(* Logix 5000 project; controller Example_PLC vendor 1 type 14 code 77 rev 19.11; software revision 19.01; part 5 of 6 *)
(* tags used below, declared in another part *)
   DISABLE : BOOL;
   ENABLE : BOOL;
   from : BOOL;
   Position : DINT;
   shutdown : BOOL;

ADD_ON_INSTRUCTION AKD_Set_Units   (* revision 2.2, ExecutePrescan, ExecuteEnableInFalse *)
// Set Drive Units for Motion Commands
// Revision note:
// Clean up instruction, especially for error recovery.
VAR_IN_OUT
   Axis : AKD_Axis; {required}
END_VAR
VAR_INPUT
   Units : SINT; {required}   // Drive Units (0=Counts 16 bit)
END_VAR
VAR_OUTPUT
   DN : BOOL; {access Read Only, visible}   // Command Successfully Initiated
   ER : BOOL; {access Read Only, visible}   // Error
END_VAR
VAR
   Set_POSUNIT : AKD_Set_Attribute := (Attribute_Number := 4);
   Set_PROFUNIT : AKD_Set_Attribute := (Attribute_Number := 5);
   Step : SINT;   // Sequence Step Number
   OS_Start_Sequence : BOOL;
   Profile_Ratio : DINT;   // The number of actual feedback counts per second or second2 equal to one velocity or acceleration unit
   Position_Ratio : DINT;   // The number of actual position feedback counts equal to one position unit
   Invalid_Input : BOOL;   // Invalid Units Input
END_VAR

ROUTINE EnableInFalse   (* ladder *)
// EnableIn_False
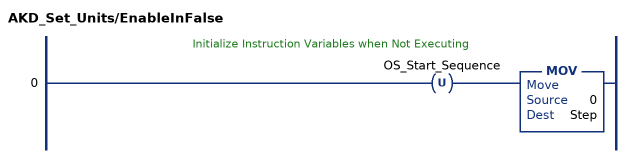
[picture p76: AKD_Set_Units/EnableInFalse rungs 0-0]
   // Initialize Instruction Variables when Not Executing
   0: OTU(OS_Start_Sequence)MOV(0,Step);
END_ROUTINE

ROUTINE Logic   (* ladder *)
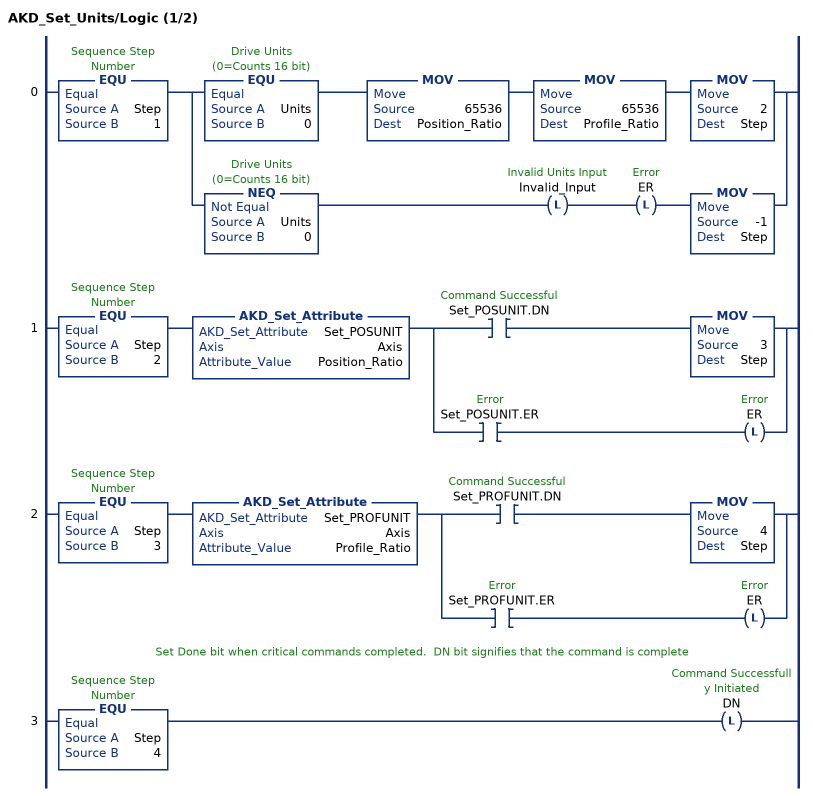
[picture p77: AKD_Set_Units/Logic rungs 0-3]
   0: EQU(Step,1)[EQU(Units,0) MOV(65536,Position_Ratio) MOV(65536,Profile_Ratio) MOV(2,Step) ,NEQ(Units,0) OTL(Invalid_Input) OTL(ER) MOV(-1,Step) ];
   1: EQU(Step,2)AKD_Set_Attribute(Set_POSUNIT,Axis,Position_Ratio)[XIC(Set_POSUNIT.DN) MOV(3,Step) ,XIC(Set_POSUNIT.ER) OTL(ER) ];
   2: EQU(Step,3)AKD_Set_Attribute(Set_PROFUNIT,Axis,Profile_Ratio)[XIC(Set_PROFUNIT.DN) MOV(4,Step) ,XIC(Set_PROFUNIT.ER) OTL(ER) ];
   // Set Done bit when critical commands completed.  DN bit signifies that the command is complete
   3: EQU(Step,4)OTL(DN);
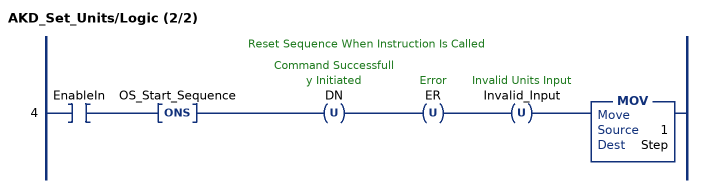
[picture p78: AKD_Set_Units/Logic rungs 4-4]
   // Reset Sequence When Instruction Is Called
   4: XIC(EnableIn)ONS(OS_Start_Sequence)OTU(DN)OTU(ER)OTU(Invalid_Input)MOV(1,Step);
END_ROUTINE

ROUTINE Prescan   (* ladder *)
// Prescan
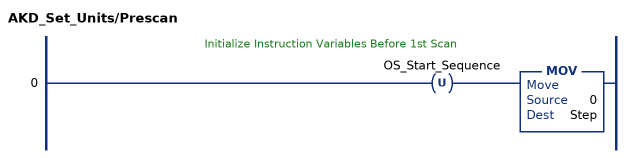
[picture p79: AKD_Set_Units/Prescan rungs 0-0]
   // Initialize Instruction Variables Before 1st Scan
   0: OTU(OS_Start_Sequence)MOV(0,Step);
END_ROUTINE
END_ADD_ON_INSTRUCTION

ADD_ON_INSTRUCTION AKD_Set_Velocity   (* revision 2.1, ExecutePrescan, ExecuteEnableInFalse *)
// Set Drive Velocity
// Revision note:
// Don't error if Command_Timeout preset is 0
VAR_OUTPUT
   DN : BOOL; {access Read Only, visible}   // Command Successful
   ER : BOOL; {access Read Only, visible}   // Error
END_VAR
VAR_IN_OUT
   Axis : AKD_Axis; {required}
END_VAR
VAR_INPUT
   Velocity : DINT; {required}   // Velocity
END_VAR
VAR
   Response_Bytes : SINT[8];
   OS_LoadStart : BOOL;
   Velocity_Internal : DINT;   // Scaled Velocity Value for Drive
   Command_Timeout : TIMER := (PRE := 100);   // Timeout Timer
   Command_Message_Type : SINT;   // Command Message Type
   Command_Axis_Number : SINT;   // Command Axis Number
   Response_Message_Type : SINT;   // Response Message Type
   Response_Axis_Number : SINT;   // Response Axis Number
   Command_Bytes : SINT[8];
   Step : SINT;
END_VAR

ROUTINE EnableInFalse   (* ladder *)
// EnableIn_False
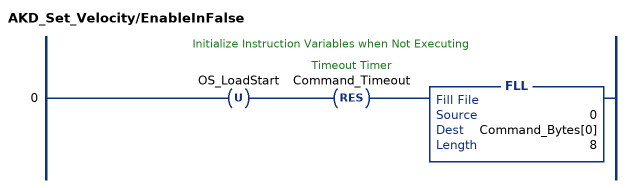
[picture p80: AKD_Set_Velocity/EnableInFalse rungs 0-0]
   // Initialize Instruction Variables when Not Executing
   0: OTU(OS_LoadStart)RES(Command_Timeout)FLL(0,Command_Bytes[0],8);
END_ROUTINE

ROUTINE Logic   (* ladder *)
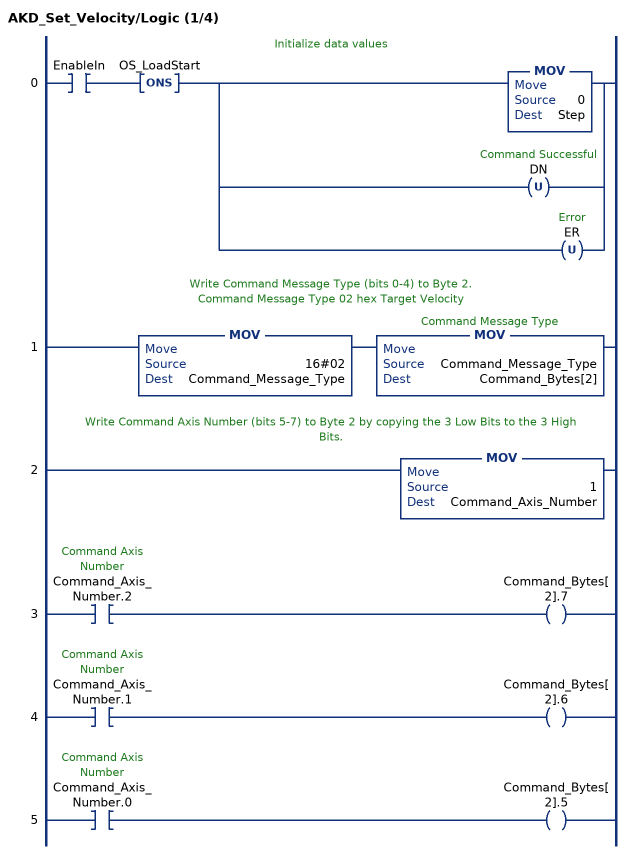
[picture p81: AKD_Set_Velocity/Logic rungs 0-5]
   // Initialize data values
   0: XIC(EnableIn)ONS(OS_LoadStart)[MOV(0,Step) ,OTU(DN) ,OTU(ER) ];
   // Write Command Message Type (bits 0-4) to Byte 2.
   // Command Message Type 02 hex Target Velocity
   1: MOV(16#02,Command_Message_Type)MOV(Command_Message_Type,Command_Bytes[2]);
   // Write Command Axis Number (bits 5-7) to Byte 2 by copying the 3 Low Bits to the 3 High Bits.
   2: MOV(1,Command_Axis_Number);
   3: XIC(Command_Axis_Number.2)OTE(Command_Bytes[2].7);
   4: XIC(Command_Axis_Number.1)OTE(Command_Bytes[2].6);
   5: XIC(Command_Axis_Number.0)OTE(Command_Bytes[2].5);
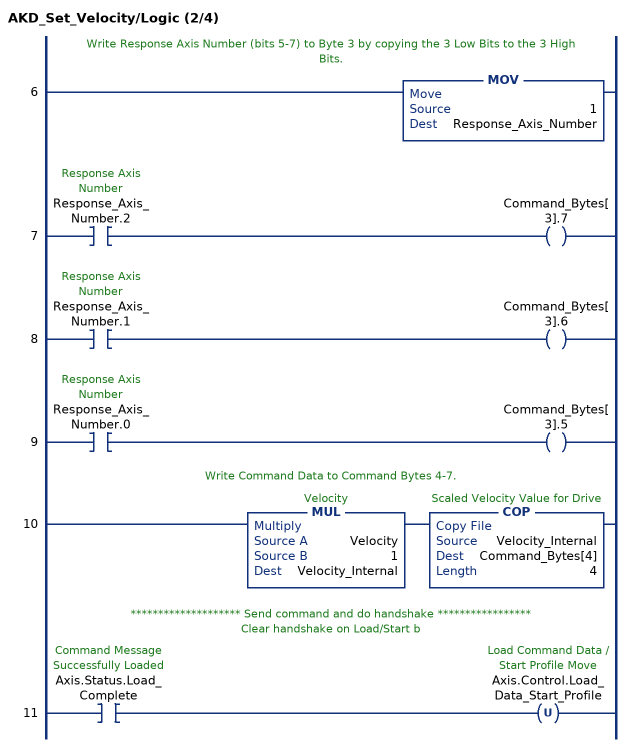
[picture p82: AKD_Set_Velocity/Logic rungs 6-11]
   // Write Response Axis Number (bits 5-7) to Byte 3 by copying the 3 Low Bits to the 3 High Bits.
   6: MOV(1,Response_Axis_Number);
   7: XIC(Response_Axis_Number.2)OTE(Command_Bytes[3].7);
   8: XIC(Response_Axis_Number.1)OTE(Command_Bytes[3].6);
   9: XIC(Response_Axis_Number.0)OTE(Command_Bytes[3].5);
   // Write Command Data to Command Bytes 4-7.
   10: MUL(Velocity,1,Velocity_Internal)COP(Velocity_Internal,Command_Bytes[4],4);
   // ******************** Send command and do handshake *****************
   // Clear handshake on Load/Start b
   11: XIC(Axis.Status.Load_Complete)OTU(Axis.Control.Load_Data_Start_Profile);
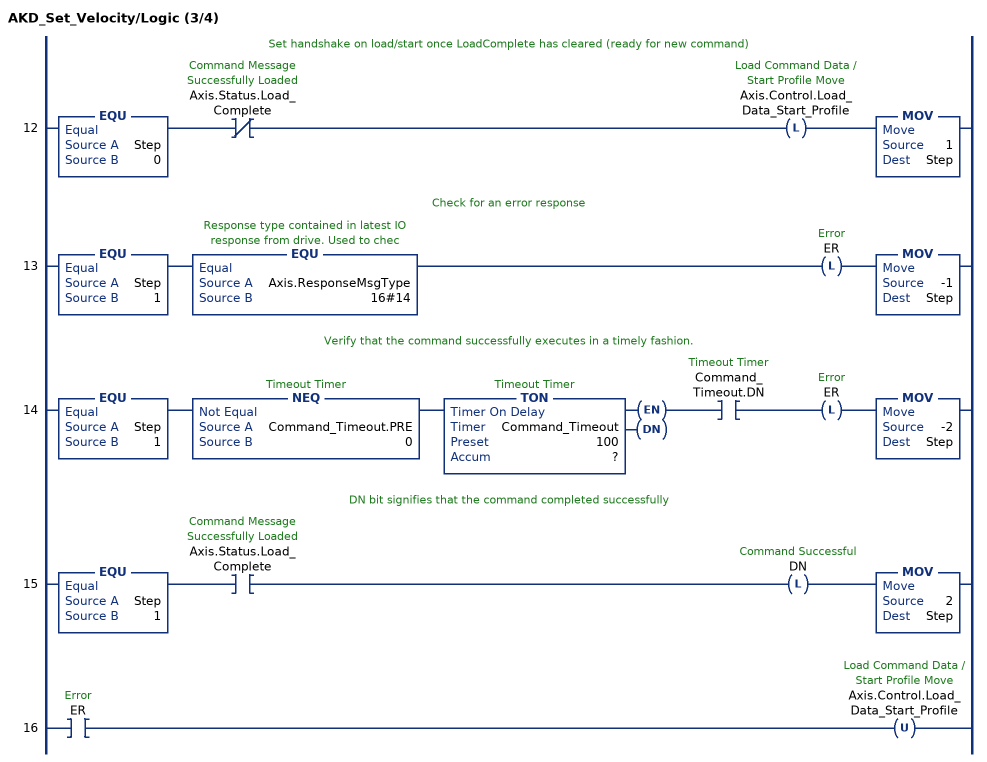
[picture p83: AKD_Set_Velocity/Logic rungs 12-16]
   // Set handshake on load/start once LoadComplete has cleared (ready for new command)
   12: EQU(Step,0)XIO(Axis.Status.Load_Complete)OTL(Axis.Control.Load_Data_Start_Profile)MOV(1,Step);
   // Check for an error response
   13: EQU(Step,1)EQU(Axis.ResponseMsgType,16#14)OTL(ER)MOV(-1,Step);
   // Verify that the command successfully executes in a timely fashion.
   14: EQU(Step,1)NEQ(Command_Timeout.PRE,0)TON(Command_Timeout,?,?)XIC(Command_Timeout.DN)OTL(ER)MOV(-2,Step);
   // DN bit signifies that the command completed successfully
   15: EQU(Step,1)XIC(Axis.Status.Load_Complete)OTL(DN)MOV(2,Step);
   16: XIC(ER)OTU(Axis.Control.Load_Data_Start_Profile);
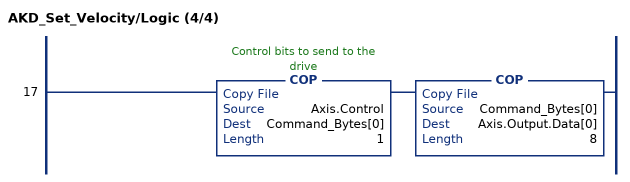
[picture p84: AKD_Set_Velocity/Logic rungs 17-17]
   17: COP(Axis.Control,Command_Bytes[0],1)COP(Command_Bytes[0],Axis.Output.Data[0],8);
END_ROUTINE

ROUTINE Prescan   (* ladder *)
// Prescan
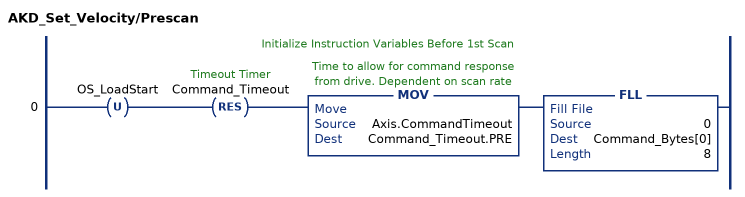
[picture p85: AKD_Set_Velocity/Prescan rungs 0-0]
   // Initialize Instruction Variables Before 1st Scan
   0: OTU(OS_LoadStart)RES(Command_Timeout)MOV(Axis.CommandTimeout,Command_Timeout.PRE)FLL(0,Command_Bytes[0],8);
END_ROUTINE
END_ADD_ON_INSTRUCTION

ADD_ON_INSTRUCTION AKD_Shutdown   (* revision 4.0, ExecutePrescan, ExecuteEnableInFalse *)
// Motion Hard Stop
// Revision note:
// There was a race with the Axis.Control.Hardstop bit.  I removed it from EnableInFalse and did the reset in the logic
VAR_OUTPUT
   DN : BOOL; {access Read Only, visible}   // Command Successful
   ER : BOOL; {access Read Only, visible}   // Error
END_VAR
VAR_IN_OUT
   Axis : AKD_Axis; {required}
END_VAR
VAR
   Command_Timeout : TIMER := (PRE := 2000);   // Timeout Timer
   Step : DINT; {access None}
END_VAR

ROUTINE EnableInFalse   (* ladder *)
// Enable In False
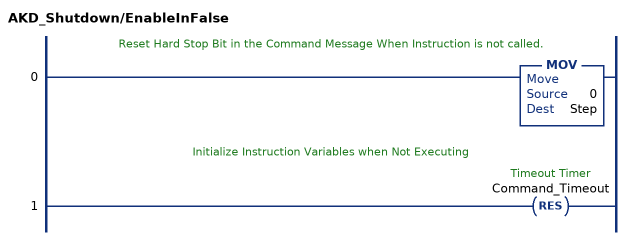
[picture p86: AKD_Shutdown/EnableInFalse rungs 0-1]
   // Reset Hard Stop Bit in the Command Message When Instruction is not called.
   0: MOV(0,Step);
   // Initialize Instruction Variables when Not Executing
   1: RES(Command_Timeout);
END_ROUTINE

ROUTINE Logic   (* ladder *)
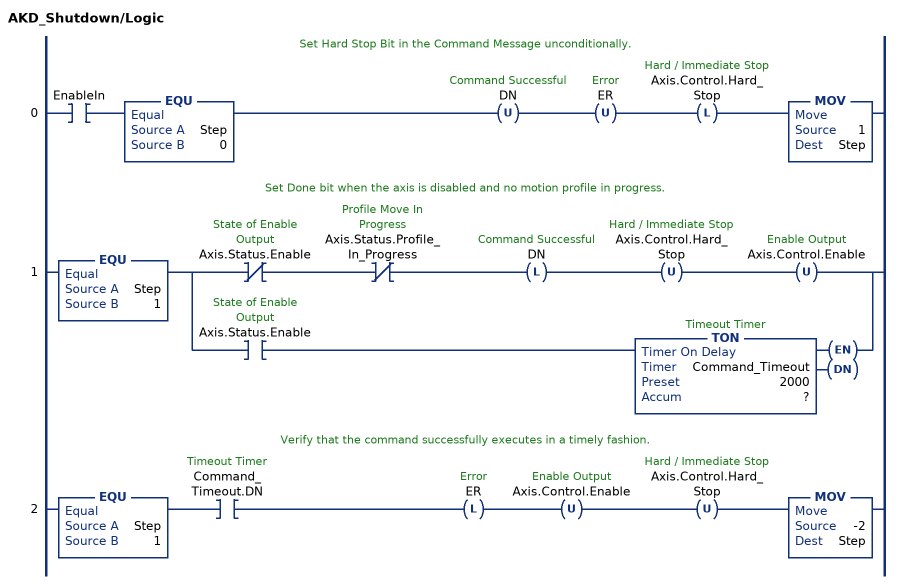
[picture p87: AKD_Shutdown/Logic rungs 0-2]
   // Set Hard Stop Bit in the Command Message unconditionally.
   0: XIC(EnableIn)EQU(Step,0)OTU(DN)OTU(ER)OTL(Axis.Control.Hard_Stop)MOV(1,Step);
   // Set Done bit when the axis is disabled and no motion profile in progress.
   1: EQU(Step,1)[XIO(Axis.Status.Enable) XIO(Axis.Status.Profile_In_Progress) OTL(DN) OTU(Axis.Control.Hard_Stop) OTU(Axis.Control.Enable) ,XIC(Axis.Status.Enable) TON(Command_Timeout,?,?) ];
   // Verify that the command successfully executes in a timely fashion.
   2: EQU(Step,1)XIC(Command_Timeout.DN)OTL(ER)OTU(Axis.Control.Enable)OTU(Axis.Control.Hard_Stop)MOV(-2,Step);
END_ROUTINE

ROUTINE Prescan   (* ladder *)
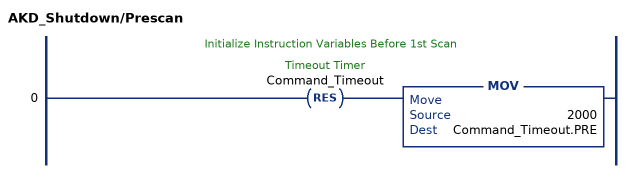
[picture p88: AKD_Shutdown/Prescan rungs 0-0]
   // Initialize Instruction Variables Before 1st Scan
   0: RES(Command_Timeout)MOV(2000,Command_Timeout.PRE);
END_ROUTINE
END_ADD_ON_INSTRUCTION

ADD_ON_INSTRUCTION AKD_Shutdown_Reset   (* revision 2.1, ExecutePrescan, ExecuteEnableInFalse *)
// Reset Drive after a Shutdown Command
// Revision note:
// Set disable timeout to 100ms
VAR_OUTPUT
   DN : BOOL; {access Read Only, visible}   // Command Successful
   ER : BOOL; {access Read Only, visible}   // Error
END_VAR
VAR_IN_OUT
   Axis : AKD_Axis; {required}
END_VAR
VAR
   Fault_Reset : AKD_Fault_Reset;
   Set_Disable : AKD_Disable;
   Step : SINT;   // Sequence Step Number
   OS_Start_Sequence : BOOL;
   Command_Timeout : TIMER := (PRE := 10000);
   Disable_Timer : TIMER := (PRE := 100);
END_VAR

ROUTINE EnableInFalse   (* ladder *)
// EnableIn_False
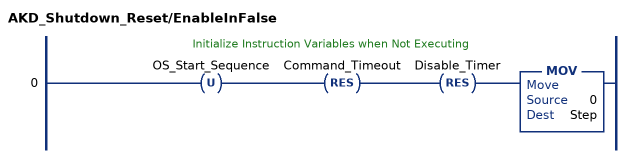
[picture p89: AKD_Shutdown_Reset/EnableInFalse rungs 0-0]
   // Initialize Instruction Variables when Not Executing
   0: OTU(OS_Start_Sequence)RES(Command_Timeout)RES(Disable_Timer)MOV(0,Step);
END_ROUTINE

ROUTINE Logic   (* ladder *)
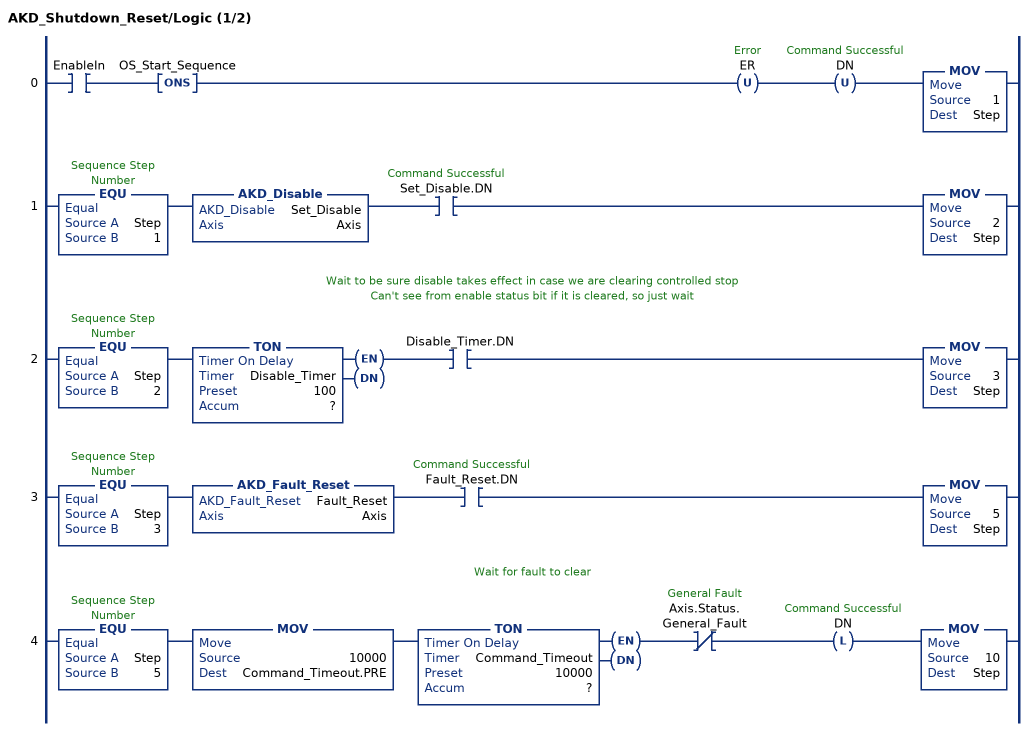
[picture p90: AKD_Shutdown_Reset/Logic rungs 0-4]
   0: XIC(EnableIn)ONS(OS_Start_Sequence)OTU(ER)OTU(DN)MOV(1,Step);
   1: EQU(Step,1)AKD_Disable(Set_Disable,Axis)XIC(Set_Disable.DN)MOV(2,Step);
   // Wait to be sure disable takes effect in case we are clearing controlled stop
   // Can't see from enable status bit if it is cleared, so just wait
   2: EQU(Step,2)TON(Disable_Timer,?,?)XIC(Disable_Timer.DN)MOV(3,Step);
   3: EQU(Step,3)AKD_Fault_Reset(Fault_Reset,Axis)XIC(Fault_Reset.DN)MOV(5,Step);
   // Wait for fault to clear
   4: EQU(Step,5)MOV(10000,Command_Timeout.PRE)TON(Command_Timeout,?,?)XIO(Axis.Status.General_Fault)OTL(DN)MOV(10,Step);
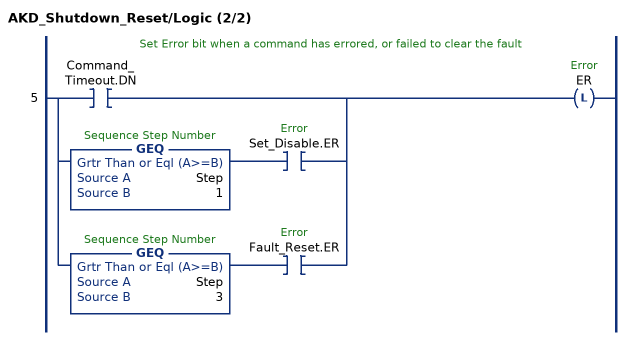
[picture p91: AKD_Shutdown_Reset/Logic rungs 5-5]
   // Set Error bit when a command has errored, or failed to clear the fault
   5: [XIC(Command_Timeout.DN) ,GEQ(Step,1) XIC(Set_Disable.ER) ,GEQ(Step,3) XIC(Fault_Reset.ER) ]OTL(ER);
END_ROUTINE

ROUTINE Prescan   (* ladder *)
// Prescan
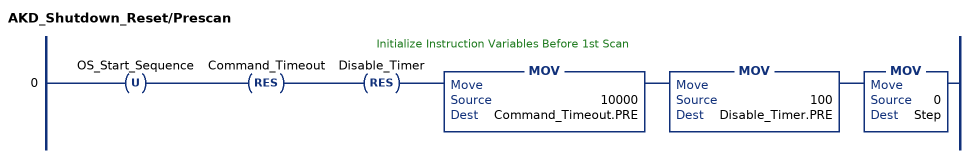
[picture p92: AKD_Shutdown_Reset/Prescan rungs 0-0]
   // Initialize Instruction Variables Before 1st Scan
   0: OTU(OS_Start_Sequence)RES(Command_Timeout)RES(Disable_Timer)MOV(10000,Command_Timeout.PRE)MOV(100,Disable_Timer.PRE)MOV(0,Step);
END_ROUTINE
END_ADD_ON_INSTRUCTION

ADD_ON_INSTRUCTION AKD_Stop_Smooth   (* revision 4.0, ExecutePrescan, ExecuteEnableInFalse *)
// Motion Smooth Stop
// Revision note:
// There was a race with the control word smooth stop bit.  I removed the logic in "EnableInFalse" and did the reset as part of the normal logic.
VAR_OUTPUT
   DN : BOOL; {access Read Only, visible}   // Command Successful
   ER : BOOL; {access Read Only, visible}   // Error
END_VAR
VAR_IN_OUT
   Axis : AKD_Axis; {required}
END_VAR
VAR_OUTPUT
   IP : BOOL; {access Read Only, visible}   // In Progress
END_VAR
VAR
   One_SHT : BOOL; {access None}
   Step : DINT; {access None}
END_VAR

ROUTINE EnableInFalse   (* ladder *)
// Enable In False
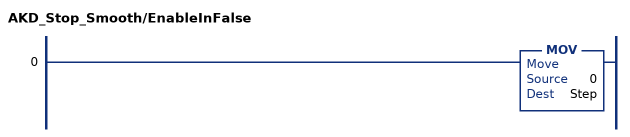
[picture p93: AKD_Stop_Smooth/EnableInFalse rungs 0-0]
   0: MOV(0,Step);
END_ROUTINE
